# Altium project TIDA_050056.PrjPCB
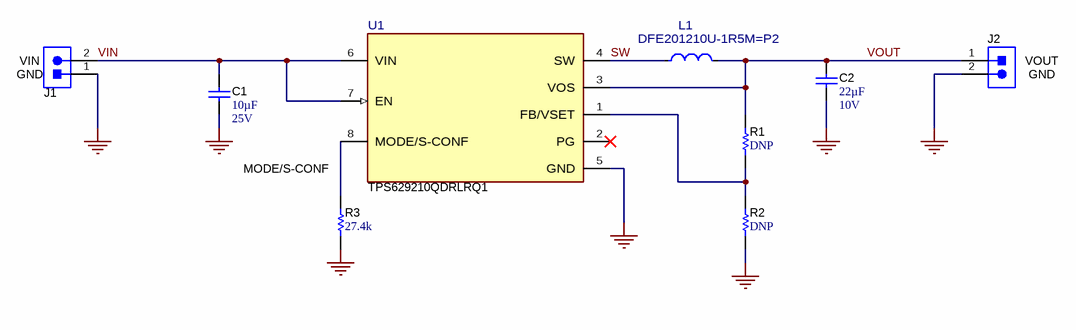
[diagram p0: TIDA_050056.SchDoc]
TIDA: TIDA-050056; TechSupport: http://www.ti.com/support; SCH_Rev: E1; PRJ_Title: TPS629210-Q1EVM; PRJ_Number: TIDA-050056; PRJ_Engineer: Nancy Zhang; PRJ_Customer: Public Release; PCB_Rev: E1; PCB_Layout: Nancy Zhang; CopyrightYear: 2021
2 sheets, 24 parts. Net scope: global (net labels, ports and power ports of the same name join across sheets).
Board file: TIDA_050056.PcbDoc
Sheets:
  TIDA_050056.SchDoc
  TIDA_050056_Hardware.SchDoc

## Sheet TIDA_050056.SchDoc
size 558 x 431 mm; Date: Not shown in title block; ApprovedBy: Not shown in title block; CheckedBy: Not shown in title block; Author: Nancy Zhang; CompanyName: Not shown in title block; DrawnBy: Nancy Zhang; Engineer: Nancy Zhang; Organization: Not shown in title block; Address1: Not shown in title block; Address2: Not shown in title block; Address3: Not shown in title block; Address4: Not shown in title block; DocumentNumber: 1; Revision: Use project parameter SCH_Rev; SheetNumber: 1; SheetTotal: 2; PageSetup: Record=PageOptions¦CenterHorizontal=True¦CenterVertical=True¦PrintScale=1.00¦XCorrection=1.00¦YCorrection=1.00¦PrintKind=0¦BorderSize=5000000¦LeftOffset=0¦BottomOffset=0¦Orientation=2¦PaperLength=1000¦PaperWidth=1000¦Scale=100¦PaperSource=15¦PrintQuality=600¦MediaType=1¦DitherType=10¦PaperKind=Letter¦PrintScaleMode=1

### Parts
C1  Cap_F: 10µF  VDC_V: 25V  [0603S]  (hidden comment: GRM188R61E106MA73D)
C2  Cap_F: 22µF  VDC_V: 10V  [0603S]  (hidden comment: GRM188R61A226ME15D)
J1  61300211121  [WURTH_61300211121]  (value not drawn)
J2  61300211121  [WURTH_61300211121]  (value not drawn)
L1  DFE201210U-1R5M=P2  [FP-DFE201210U-1R5M=P2_0805 (2012)-MFG]
R1  ValueDisplayed: DNP  [0402S]  (hidden comment: CRCW0402154KFKED)
R2  ValueDisplayed: DNP  [0402S]  (hidden comment: CRCW040234K0FKED)
R3  ValueDisplayed: 27.4k  [0402S]  (hidden comment: CRCW040227K4FKED)
U1  TPS629210QDRLRQ1  [DRL0008A-MFG]

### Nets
GND: C1.2 C2.2 J1.1 J2.2 R2.1 R3.1 U1.5(GND)
SW: L1.1 U1.4(SW)
VIN: C1.1 J1.2 U1.6(VIN) U1.7(EN)
VOUT: C2.1 J2.1 L1.2 R1.2 U1.3(VOS)
NetR1_1: R1.1 R2.2 U1.1(FB/VSET)
NetR3_2: R3.2 U1.8(MODE/S-CONF)

Not connected (* = marked no-connect by the designer): U1 2(PG)*

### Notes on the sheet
- (near J1) VIN
- (near J1) GND
- (near J2) VOUT
- (near J2) GND
- MODE/S-CONF

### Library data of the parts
C1 = CMP-0007344-5: CAP, CERM, 10 uF, 25 V, +/- 20%, X5R, 0603; Manufacturer: MuRata; SizeAreaWB_mm2: 4.68; SizeArea_mm2: 1.28; AEC Category: Q200; Value: 10uF; TaMax_C: 85°C; SizeZ_mm: 1; Polarized: N; TaMin_C: -55°C; SizeY_mm: 0.8; U/M: EA; SizeX_mm: 1.6; Cap_Case: 0603; Value1: Unknown
C2 = CMP-0007324-5: CAP, CERM, 22 uF, 10 V, +/- 20%, X5R, 0603; Manufacturer: MuRata; SizeY_mm: 0.8; Cap_Case: 0603; SizeArea_mm2: 1.28; AEC Category: Q200; ValueDisplayed: 22uF; TaMin_C: -55°C; Polarized: N; SizeAreaWB_mm2: 4.68; Value1: Unknown; U/M: EA; Value: 22uF; TaMax_C: 85°C; SizeZ_mm: 1; SizeX_mm: 1.6
J1 J2 = CMP-0054794-2: Header, 2.54 mm, 2x1, Gold, TH; Manufacturer: Wurth Elektronik; Shrouded: N; Gender: Male; Green_REACh: Passed; Pitch_mm: 2.54; Green_Lifecycle: Active; Row_Count: 1; Cert_UL: Y
L1 = CMP-0093854-1: 1.5µH Shielded Wirewound Inductor 1.6A 138mOhm Max 0805 (2012 Metric); Manufacturer: Murata; Shrouded: true; Material: Metal Alloy; AEC Qualified: No; Test Frequency: 1MHz; DCR_ohm: 0.138; Isat: 2.5A; Tolerance_%: 20%; Value: 1.5uH; SizeZ_mm: 1mm
R1 = CMP-0026023-3: RES, 154 k, 1%, 0.063 W, AEC-Q200 Grade 0, 0402; Manufacturer: Vishay-Dale; Power_W: 63mW; TempCo: 100 ppm/C; Value_Code: 154k; Value: 154k; EIA_Code: E96; SizeX_mm: 1; SizeY_mm: 0.5; SizeZ_mm: 0.6; Value2: 0.063W; AEC Qualified: Y; VDC_V: 50V; AEC Category: Q200; AEC Grade: 0
R2 = CMP-0026304-2: RES, 34.0 k, 1%, 0.063 W, AEC-Q200 Grade 0, 0402; Manufacturer: Vishay-Dale; Power_W: 63mW; TempCo: 100 ppm/C; Value_Code: 34k0; Value: 34.0k; EIA_Code: E96; Res_ohm: 34k; SizeX_mm: 1; SizeZ_mm: 0.6; Value2: 0.063W; SizeArea_mm2: 0.5; AEC Qualified: Y; VDC_V: 50V; AEC Category: Q200; AEC Grade: 0
R3 = CMP-0026213-2: RES, 27.4 k, 1%, 0.063 W, AEC-Q200 Grade 0, 0402; Manufacturer: Vishay-Dale; Power_W: 63mW; TempCo: 100 ppm/C; Value_Code: 27k4; Value: 27.4k; EIA_Code: E96; SizeX_mm: 1; SizeY_mm: 0.5; SizeZ_mm: 0.6; Value2: 0.063W; AEC Qualified: Y; VDC_V: 50V; AEC Category: Q200; AEC Grade: 0
U1 = CMP-0089687-1: 3-V to 17-V, Synchronous Buck Converters in 1.6 mm x 2.1 mm SOT583 Package; Manufacturer: Texas Instruments; AEC Qualified: Yes; Standoff Height: 0mm; Output Voltage: 0.4-5.5V; Nominal Supply Current: 8mA; SizeZ_mm: 0.6mm; Number Of Outputs: 1; TJmax_C: +150°C; Output Type: AdjustableProgrammable; Max Supply Voltage: 17V; Min Supply Voltage: 3V; Switching Frequency: 2.5MHz

## Sheet TIDA_050056_Hardware.SchDoc
size 431 x 279 mm; Date: Not shown in title block; ApprovedBy: Not shown in title block; CheckedBy: Not shown in title block; Author: Nancy Zhang; CompanyName: Not shown in title block; DrawnBy: Nancy Zhang; Engineer: Nancy Zhang; Organization: Not shown in title block; Address1: Not shown in title block; Address2: Not shown in title block; Address3: Not shown in title block; Address4: Not shown in title block; DocumentNumber: 2; Revision: Use project parameter SCH_Rev; SheetNumber: 2; SheetTotal: 2; PageSetup: Record=PageOptions¦CenterHorizontal=True¦CenterVertical=True¦PrintScale=1.00¦XCorrection=1.00¦YCorrection=1.00¦PrintKind=0¦BorderSize=5000000¦LeftOffset=0¦BottomOffset=0¦Orientation=2¦PaperLength=1000¦PaperWidth=1000¦Scale=100¦PaperSource=15¦PrintQuality=600¦MediaType=1¦DitherType=10¦PaperKind=Letter¦PrintScaleMode=1
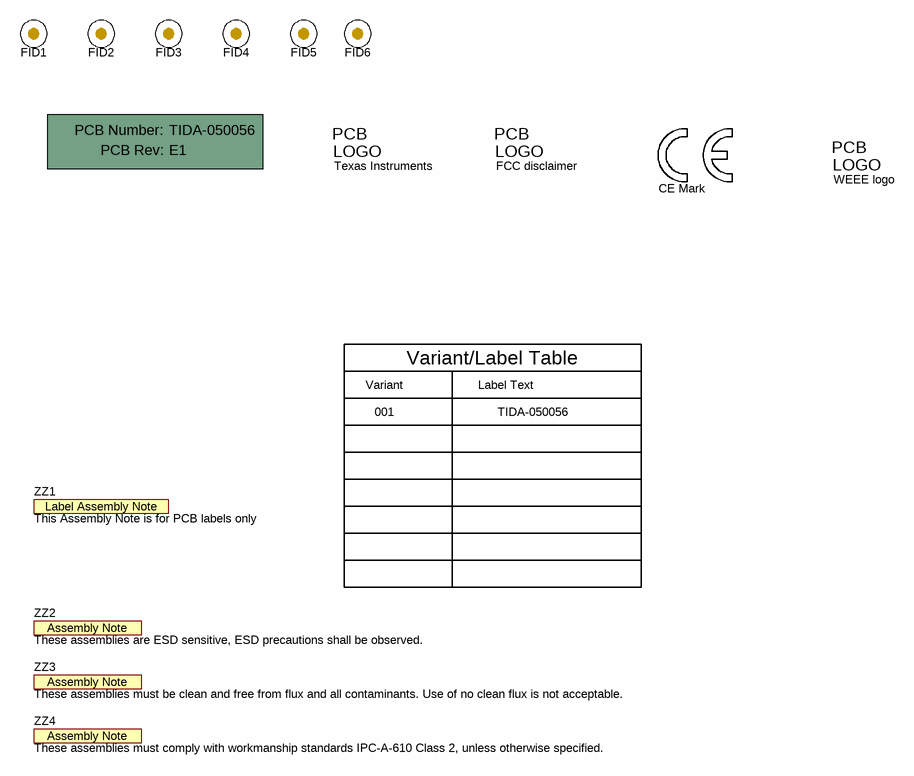
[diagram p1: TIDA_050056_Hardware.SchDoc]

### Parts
!PCB  Printed Circuit Board  (value not drawn)  (mechanical)
FID1  Fiducial  [Fiducial10-20]  (value not drawn)
FID2  Fiducial  [Fiducial10-20]  (value not drawn)
FID3  Fiducial  [Fiducial10-20]  (value not drawn)
FID4  Fiducial  [Fiducial10-20]  (value not drawn)
FID5  Fiducial  [Fiducial10-20]  (value not drawn)
FID6  Fiducial  [Fiducial10-20]  (value not drawn)
LOGO1  Texas Instruments  [TI_Symbol_Overlay_Small]  (no BOM)
Logo3  FCC disclaimer  [FCC_disclaimer_stacked]  (no BOM)
LOGO4  CE Mark  [CE_Mark_5mm]  (no BOM)
Logo5  WEEE logo  [WEEE_Minimum]  (no BOM)
ZZ1  This Assembly Note is for PCB labels only  [AssemblyNoteLabel]  (no BOM)
ZZ2  These assemblies are ESD sensitive, ESD precautions shall be observed.  [AssemblyNote]  (no BOM)
ZZ3  These assemblies must be clean and free from flux and all contaminants. Use of no clean flux is not acceptable.  [AssemblyNote]  (no BOM)
ZZ4  These assemblies must comply with workmanship standards IPC-A-610 Class 2, unless otherwise specified.  [AssemblyNote]  (no BOM)

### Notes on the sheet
- Variant
- Variant/Label Table
- Label Text
- 001
- TIDA-050056

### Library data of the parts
!PCB = CMP-0003618-2: PartNumber: TIDA-050056; Manufacturer: Any
FID1-FID6 = CMP-0077181-1: Fiducial mark.  There is nothing to buy or mount.
LOGO1 = CMP-0074838-1: Texas Instrument Corporate Signature; SymbolCreator: a0412235; Lib Reference: TI_Logo
Logo3 = CMP-0074847-1: FCC_disclaimer
LOGO4 = CMP-0074844-1: SymbolCreator: a0412235
Logo5 = CMP-0074769-1
ZZ1 = CMP-0003616-3
ZZ2 = CMP-0077236-1
ZZ3 = CMP-0077237-1
ZZ4 = CMP-0077238-1

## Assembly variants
001: not fitted FID1 FID2 FID3 FID4 FID5 FID6 R1 R2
